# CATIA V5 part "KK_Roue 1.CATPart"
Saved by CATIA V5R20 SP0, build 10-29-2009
Part number: Roue 1
Bounding box of the stored display mesh (mm): x 256 to 704, y 176.046 to 1935.954, z -3951.98 to -2192.02
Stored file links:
  G:\Khaled_CFAO_2011\ST2M\ST2M_GR2\aboulegue\Khaled\CAD_thinkMOTION\KK_Roue 1.CATPart
  G:\Khaled_CFAO_2011\ST2M\ST2M_GR2\aboulegue\Khaled\CAD_thinkMOTION\KK_Train_Atterrissage.CATProduct
  G:\Khaled_CFAO_2011\ST2M\ST2M_GR2\aboulegue\Khaled\CAD_thinkMOTION\KK_Squelette_Roue_1.CATPart
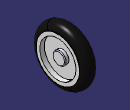
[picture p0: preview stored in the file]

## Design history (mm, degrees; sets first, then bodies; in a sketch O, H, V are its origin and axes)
Set1
  Plane1 "Plan roue 1": linked copy from another document
  Line1: linked copy from another document
  Line2: linked copy from another document
  Point1: linked copy from another document
  Point2: linked copy from another document
Body1 (main body)
  Sketch1 on Plane1, origin (0, 1056, 0), H (1, 0, 0), V (0, 0, 1)
    line L1 (256, -2400) -> (256, -2512)
    line L2 (256, -2512) -> (400, -2512)
    line L3 (400, -2512) -> (400, -2872)
    line L4 (400, -2872) -> (288, -2872)
    line L5 (288, -2872) -> (288, -3072)
    line L6 (288, -3072) -> (672, -3072)
    line L7 (672, -3072) -> (672, -2872)
    point P8 (672, -2872)
    line L8 (672, -2872) -> (560, -2872)
    line L9 (560, -2872) -> (560, -2512)
    point P10 (560, -2512)
    line L10 (560, -2512) -> (704, -2512)
    line L11 (704, -2512) -> (704, -2400)
    line L12 (256, -2400) -> (272, -2400)
    line L13 (272, -2400) -> (272, -2496)
    line L14 (272, -2496) -> (688, -2496)
    line L15 (688, -2496) -> (688, -2400)
    point P16 (688, -2400)
    line L16 (688, -2400) -> (704, -2400)
    reference projected line E1 (480, -3072) -> (480, -2400) from Line1
    reference projected line E2 (280, -3072) -> (680, -3072) from Line2
    reference projected line E3 (480, -3072) -> (480, -2400) from Line1
    length L6 = 384
    length L4 = 112
    length L2 = 144
    length L1 = 112
    distance E1 L13 = 208
    length L5 = 200
    length L10 = 144
    length L8 = 112
    distance L16 L6 = 672
    distance L3 E3 = 80
    length L13 = 96
    length L14 = 416
    vertical: L1 V, L3 V, L5 V, L7 V, L9 V, L11 V, L13 V, L15 V
    horizontal: L2 H, L4 H, L6 H, L8 H, L10 H, L12 H, L14 H, L16 H
    coincidence: P8 L4, P10 L2, P16 L12, L6 E2
  Shaft1: profile Sketch1, axis Line2, angle 360
  Sketch2 on Plane1, origin (0, 1056, 0), H (1, 0, 0), V (0, 0, 1)
    arc A1 centre (480, -2400) radius 208 from (688, -2400) to (272, -2400) ccw
    point P1 (480, -2400)
    reference projected point E1 (480, -2400) from Point1
    line L1 (272, -2400) -> (688, -2400)
    radius A1 = 208
    length L1 = 416
    coincidence: P1 E1
    horizontal: L1 H
  Shaft2: profile Sketch2, axis Line2, angle 360
  Sketch3 on face of Shaft1 from Sketch1.L5, origin (288, 0, 0), H (0, -1, 0), V (0, 0, 1)
    circle A1 centre (-1056, -3072) radius 160
    point P1 (-1056, -3072)
    reference projected point E1 (-1056, -3072) from Point2
    radius A1 = 160
    coincidence: E1 P1
  Pocket1: profile Sketch3, direction (1, 0, 0), length 192
  Fillet1: radius 25, on edge [face of Shaft1 from Sketch1.L8 | face of Shaft1 from Sketch1.L7]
